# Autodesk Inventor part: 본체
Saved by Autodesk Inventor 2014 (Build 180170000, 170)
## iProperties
Created: 2026-03
Part Number: 본체
Material: 알루미늄 6061
Document SubType Name: Modeling
Designer: dg
Density: 2.71 g/cm^3
Appearance: 알루미늄 - 평지
Author: jhkim
Creation Date: 2025-06-27
Sending System: Autodesk Inventor 2026
Preprocessor: ST-DEVELOPER v20.1
Author: dg
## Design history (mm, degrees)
node "본체1"
node "솔리드1"
node "기준1"
